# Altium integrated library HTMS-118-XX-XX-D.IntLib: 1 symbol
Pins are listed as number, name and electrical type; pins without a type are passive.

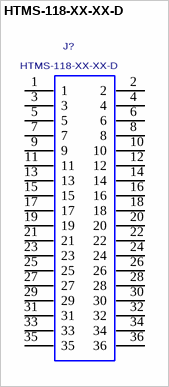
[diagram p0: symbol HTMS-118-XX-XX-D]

## HTMS-118-XX-XX-D
designator J?
HI-TEMP TERMINAL MICOR-STRIP.; MANUFACTURER: SAMTEC
footprint HTMS-118-XX-XX-D
pins: 1, 2, 3, 4, 5, 6, 7, 8, 9, 10, 11, 12, 13, 14, 15, 16, 17, 18, 19, 20, 21, 22, 23, 24, 25, 26, 27, 28, 29, 30, 31, 32, 33, 34, 35, 36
